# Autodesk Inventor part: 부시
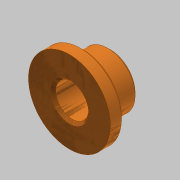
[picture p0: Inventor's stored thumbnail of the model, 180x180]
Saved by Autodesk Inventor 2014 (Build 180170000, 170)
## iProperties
Created: 2016-02
Part Number: 부시
Material: 스테인리스강
Document SubType Name: Modeling
Designer: mduedu
Density: 8.08 g/cm^3
Appearance: Metal 1600F Hot
Mass: 39.4553 g
Surface Area: 27.3717 cm^2
Volume: 4.88308 cm^3
Author: mduedu
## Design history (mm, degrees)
sketch "스케치1"
  geometry: C1 r 15 at (0, 0); 1 further point
  constraints: 1 centre point, 1 coincident
  dimensions: "d0" = 30 diameter of C1
extrude "돌출1" new body sketch "스케치1" distance "d1" = 5; taper "d2" = 0 deg
sketch "스케치2"
  geometry: C1 r 10 at (0, 0); 1 further point
  constraints: 1 centre point, 1 coincident
  dimensions: "d3" = 20 diameter of C1
extrude "돌출2" join sketch "스케치2" distance "d4" = 10; taper "d5" = 0 deg
hole "구멍1" diameter "d8" = 12; stored, may be unused: countersink angle "d12" = 90 deg, drill point angle "d14" = 118 deg; dims "d9" = 6, "d10" = 4, "d11" = 2, "d13" = 8, "d15" = 10, "d16" = 10
chamfer "모따기1" distance "d17" = 1; stored, may be unused: second distance "d18" = 2, angle "d19" = 45 deg
chamfer "모따기2" distance "d20" = 1; stored, may be unused: second distance "d21" = 2, angle "d22" = 45 deg
chamfer "모따기3" distance "d23" = 1; stored, may be unused: second distance "d24" = 2, angle "d25" = 45 deg
node "솔리드1"
